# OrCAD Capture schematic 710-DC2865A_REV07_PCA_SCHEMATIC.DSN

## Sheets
1 PAGE2-HARDWARE
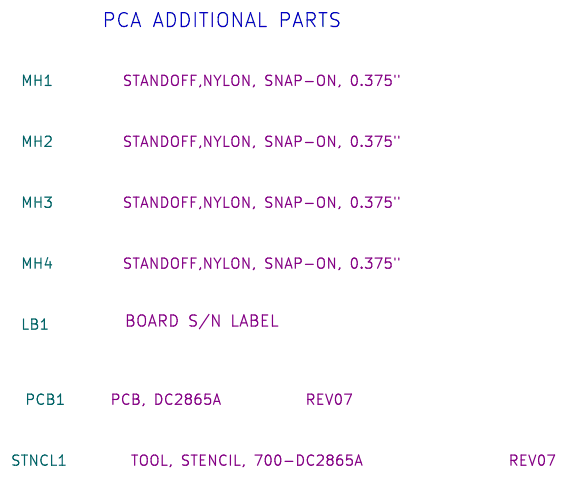
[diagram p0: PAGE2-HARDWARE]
2 PAGE1-LT8393JFE: size Custom; note: LED CONTROLLER
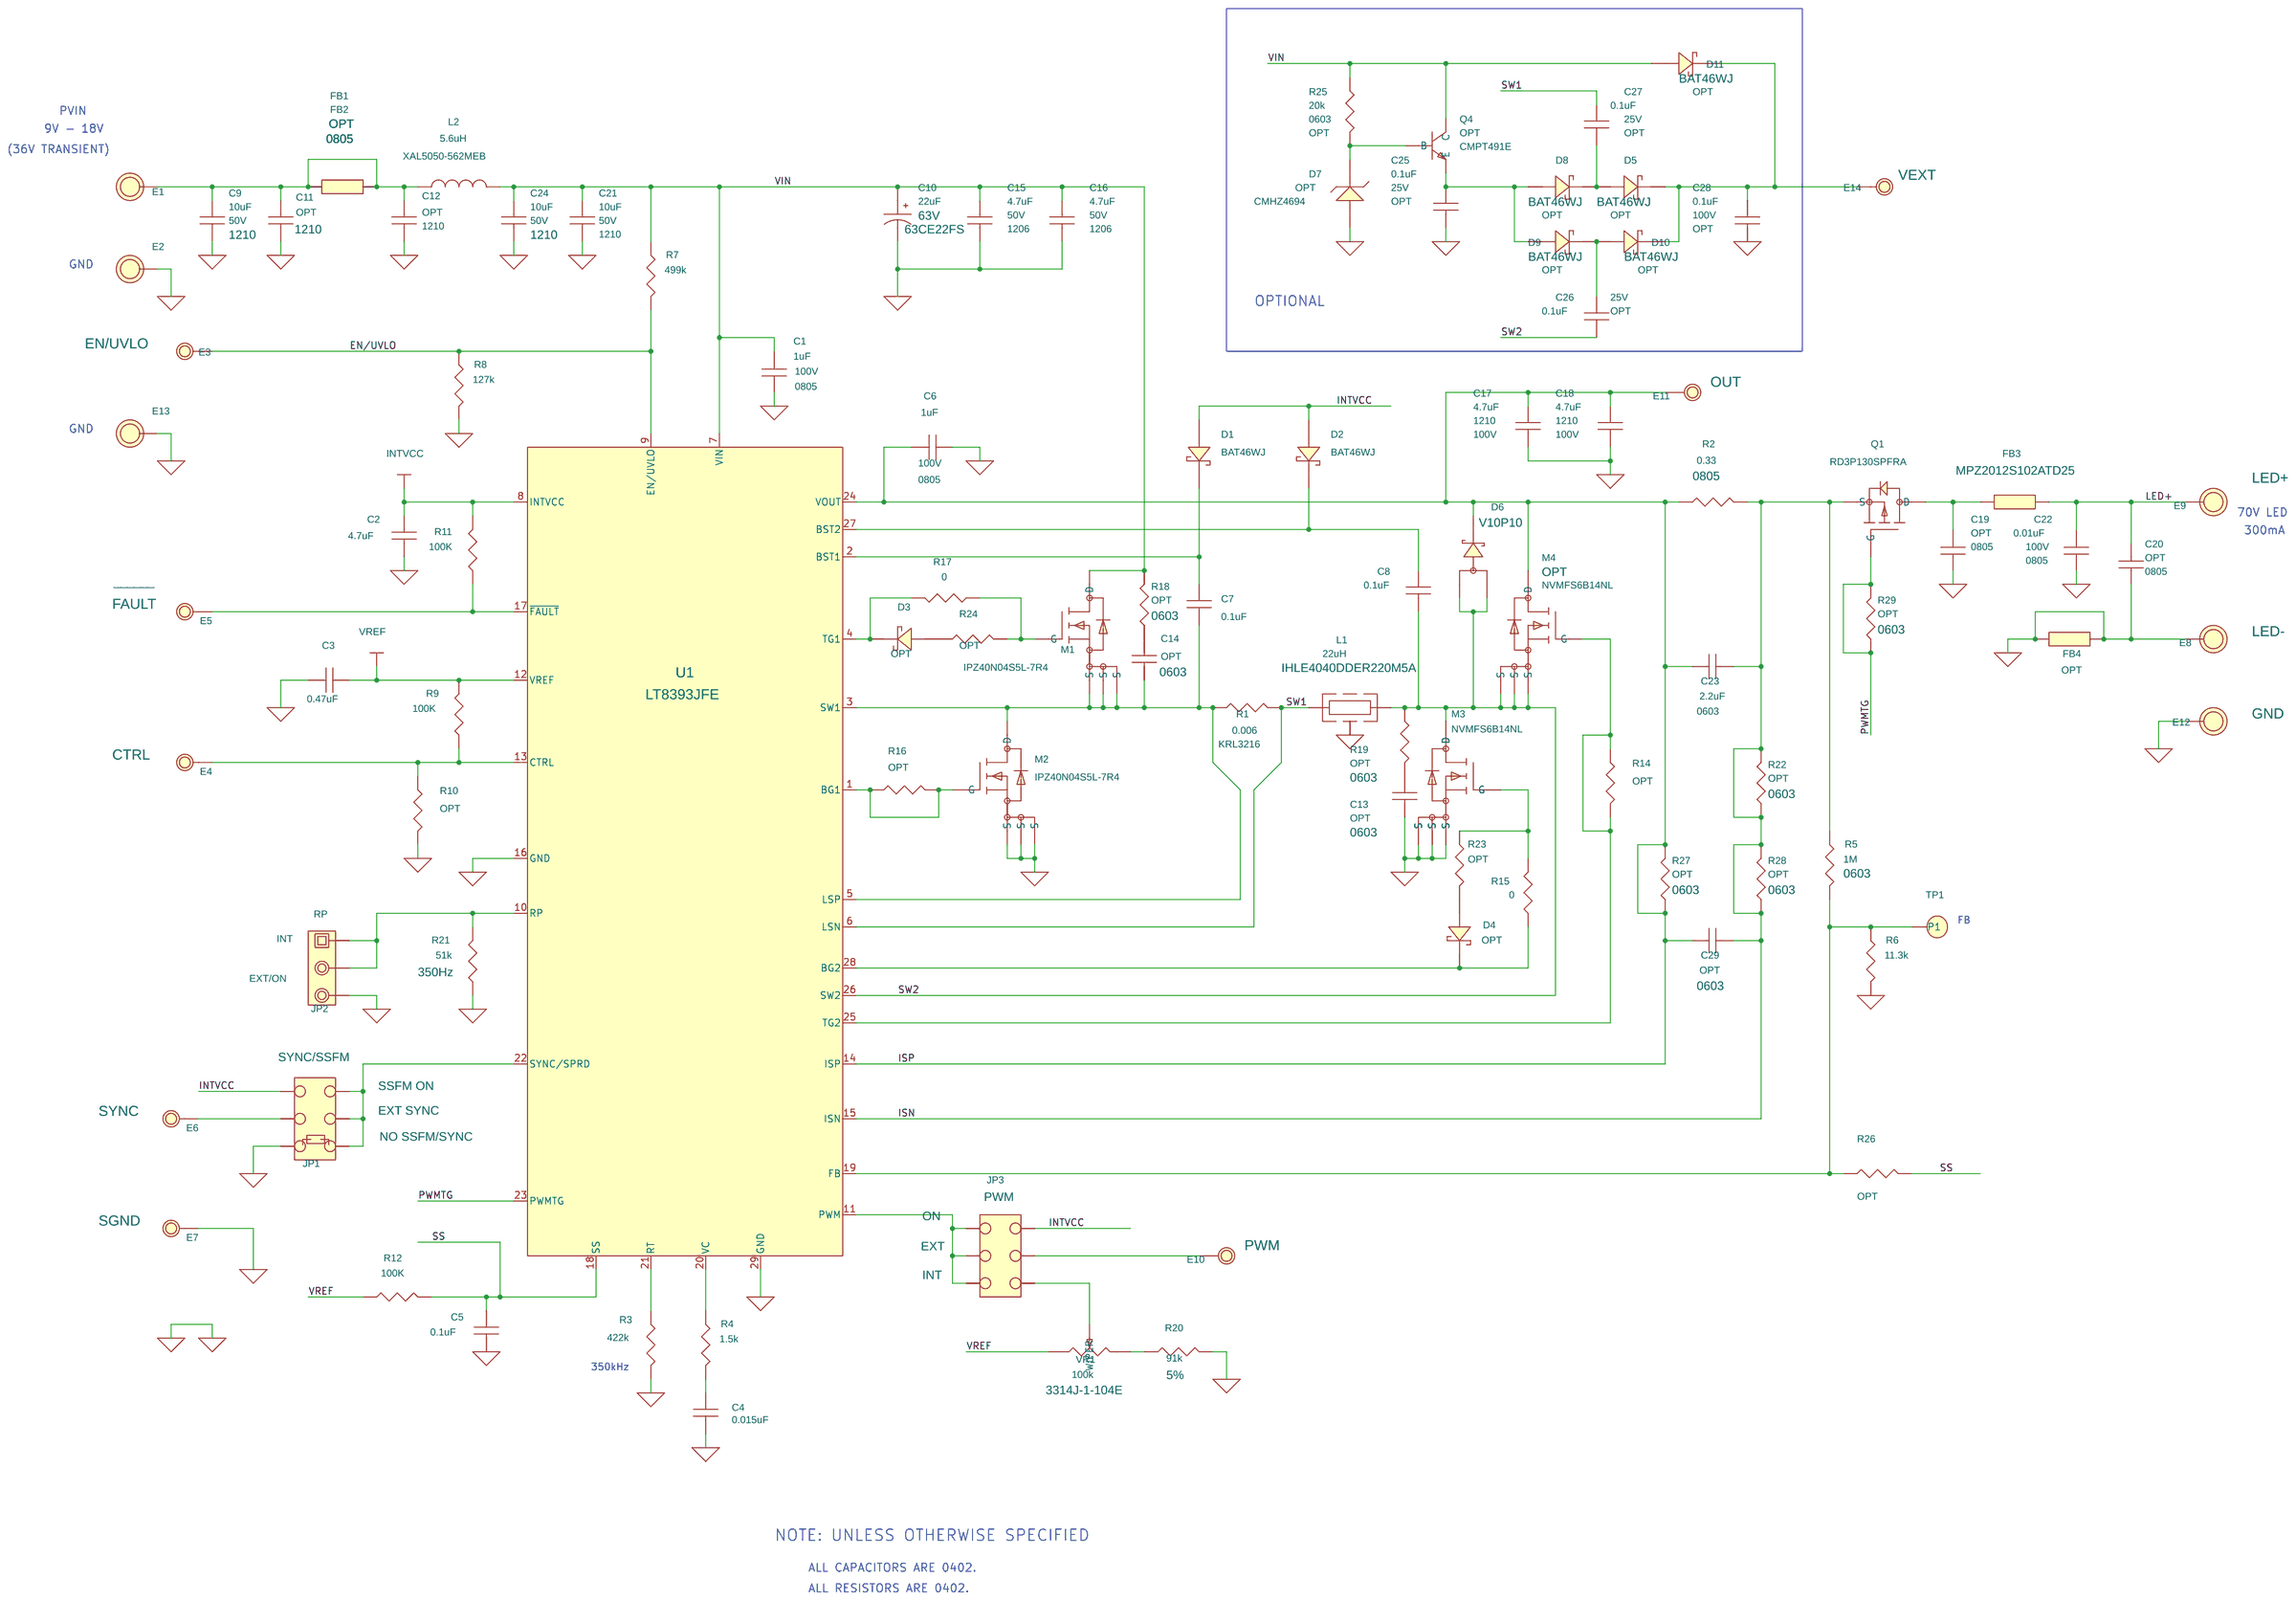
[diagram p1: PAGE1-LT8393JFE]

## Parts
sheet PAGE1-LT8393JFE
C1  1uF  [CC0805N]
C2  4.7uF  [CC0402N]
C3  0.47uF  [CC0402N]
C4  0.015uF  [CC0402N]
C5  0.1uF  [CC0402N]
C6  1uF  [CC0805N]
C7  0.1uF  [CC0402N]
C8  0.1uF  [CC0402N]
C9  10uF  [CC1210N]
C10  22uF  [SUNCON_CE-FS_6.3X7.7]
C11  OPT  [CC1210N]
C12  OPT  [CC1210N]
C13  OPT  [CC0603N]
C14  OPT  [CC0603N]
C15  4.7uF  [CC1206N]
C16  4.7uF  [CC1206N]
C17  4.7uF  [CC1210N]
C18  4.7uF  [CC1210N]
C19  OPT  [CC0805N]
C20  OPT  [CC0805N]
C21  10uF  [CC1210N]
C22  0.01uF  [CC0805N]
C23  2.2uF  [CC0603N]
C24  10uF  [CC1210N]
C25  0.1uF  [CC0402N]
C26  0.1uF  [CC0402N]
C27  0.1uF  [CC0402N]
C28  0.1uF  [CC0402N]
C29  OPT  [CC0603N]
D1  BAT46WJ  [SOD-323F-N]
D2  BAT46WJ  [SOD-323F-N]
D3  OPT  [SOD-523N]
D4  OPT  [SOD-523N]
D5  BAT46WJ  [SOD-323F-N]
D6  V10P10  [VISHAY-TO-277A_SMPC]
D7  OPT  [SOD-123N]
D8  BAT46WJ  [SOD-323F-N]
D9  BAT46WJ  [SOD-323F-N]
D10  BAT46WJ  [SOD-323F-N]
D11  BAT46WJ  [SOD-323F-N]
E1  TEST POINT  [MILLMAX2501]
E2  TEST POINT  [MILLMAX2501]
E3  TEST POINT  [MILLMAX2308]
E4  TEST POINT  [MILLMAX2308]
E5  TEST POINT  [MILLMAX2308]
E6  TEST POINT  [MILLMAX2308]
E7  TEST POINT  [MILLMAX2308]
E8  TEST POINT  [MILLMAX2501]
E9  TEST POINT  [MILLMAX2501]
E10  TEST POINT  [MILLMAX2308]
E11  TEST POINT  [MILLMAX2308]
E12  TEST POINT  [MILLMAX2501]
E13  TEST POINT  [MILLMAX2501]
E14  TEST POINT  [MILLMAX2308]
FB1  OPT  [IND0805N]
FB2  OPT  [IND0805N]
FB3  1k OHM@100MHz  [IND0805N]
FB4  1k OHM@100MHz  [IND0805N]
JP1  HDR  [HD2X3-079]
JP2  HDR  [HD1X3-079]
JP3  HDR  [HD2X3-079]
L1  22uH  [VISHAY-IHLE-4040DD-5A]
L2  5.6uH  [COILCRAFT-XAL50]
M1  IPZ40N04S5L-7R4  [INFINEON-PG-TSDSON-8-32]
M2  IPZ40N04S5L-7R4  [INFINEON-PG-TSDSON-8-32]
M3  NVMFS6B14NL  [ONSEMI-DFN5-SO-8FL]
M4  NVMFS6B14NL  [ONSEMI-DFN5-SO-8FL]
Q1  RD3P130SPFRA  [TO-252-3N]
Q4  OPT  [SOT23-3N]
R1  0.006  [SUSUMU-KRL3216]
R2  0.33  [CR0805N]
R3  422k  [CR0402N]
R4  1.5k  [CR0402N]
R5  1M  [CR0603N]
R6  11.3k  [CR0402N]
R7  499k  [CR0402N]
R8  127k  [CR0402N]
R9  100K  [CR0402N]
R10  OPT  [CR0402N]
R11  100K  [CR0402N]
R12  100K  [CR0402N]
R14  OPT  [CR0402N]
R15  0  [CR0402N]
R16  OPT  [CR0402N]
R17  0  [CR0402N]
R18  OPT  [CR0603N]
R19  OPT  [CR0603N]
R20  91k  [CR0402N]
R21  51k  [CR0402N]
R22  OPT  [CR0603N]
R23  OPT  [CR0402N]
R24  OPT  [CR0402N]
R25  20k  [CR0603N]
R26  OPT  [CR0402N]
R27  OPT  [CR0603N]
R28  OPT  [CR0603N]
R29  OPT  [CR0603N]
TP1  TEST PAD  [TEST-PIN]
U1  LT8393JFE  [LTC-FE-28-1663]
VR1  100k  [BOURNES-3314J]
XJP1  SHUNT
XJP2  SHUNT
XJP3  SHUNT
sheet PAGE2-HARDWARE
LB1  LABEL  [895-0154_REV01]
MH1  STANDOFF  [WURTH-7029]
MH2  STANDOFF  [WURTH-7029]
MH3  STANDOFF  [WURTH-7029]
MH4  STANDOFF  [WURTH-7029]
PCB1  PCB, DC2865A  [MECHANICAL_PART]
STNCL1  TOOL, STENCIL, 700-DC2865A

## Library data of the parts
C1 C6 = CAP: CAP.,1uF,X7S,100V,10%,0805,AEC-Q200,NO SUBS. ALLOWED; CLASS: DISCRETE; Dielectric Type: X7S; FPLIST: CC0805N,CC0805L,CC0805M; Inventory Qty: 11870; Manufacturer: MURATA; Manufacturer PN: GCM21BC72A105KE36L; PART_NUMBER: 150-1770; Package Size: 0805; Rated Voltage: 100V; Temperature Coefficient: X7S; Tolerance: 10%
C2 = CAP: CAP.,4.7uF,X5R,10V,10%,0402; CLASS: DISCRETE; Dielectric Type: X5R; FPLIST: CC0402N,CC0402L,CC0402M; Inventory Qty: 30305; Manufacturer: TDK; Manufacturer PN: C1005X5R1A475K050BC; PART_NUMBER: 150-2275; Package Size: 0402; Rated Voltage: 10V; Tolerance: 10%
C3 = CAP: CAP.,0.47uF,X5R,16V,10%,0402; CLASS: DISCRETE; Dielectric Type: X5R; Inventory Qty: 1178; Manufacturer: AVX; Manufacturer PN: 0402YD474KAT2A; PART_NUMBER: 150-3431; Package Size: 0402; Rated Voltage: 16V; Tolerance: 10%
C4 = CAP: CAP.,0.015uF,X7R,16V,10%,0402; CLASS: DISCRETE; Dielectric Type: X7R; Inventory Qty: 30000; Manufacturer: AVX; Manufacturer PN: 0402YC153KAT2A; PART_NUMBER: 150-2639; Package Size: 0402; Package Type: SMD; Rated Voltage: 16V; Tolerance: 10%
C5 C7 C8 = CAP: CAP.,0.1uF,X7R,25V,10%,0402; CLASS: DISCRETE; Dielectric Type: X7R; FPLIST: CC0402N,CC0402L,CC0402M; Inventory Qty: 44848; Manufacturer: AVX; Manufacturer PN: 04023C104KAT2A; PART_NUMBER: 150-2276; Package Size: 0402; Rated Voltage: 25V; Tolerance: 10%
C9 C24 = CAP: CAP.,10uF,X7S,50V,10%,1210,AEC-Q200; CLASS: DISCRETE; Dielectric Type: X7S; FPLIST: CC1210N,CC1210L,CC1210M; Inventory Qty: 0; Manufacturer: MURATA; Manufacturer PN: GCM32EC71H106KA03L; PART_NUMBER: 150-2617; Package Size: 1210; Rated Voltage: 50V; Tolerance: 10%
C10 = CAP_P_ALT: CAP.,22uF,ALUM,63V,20%,SMD 6.3x7.7mm; CLASS: DISCRETE; Dielectric Type: ALUM; Inventory Qty: 8770; Manufacturer: SUN ELECTRONIC INDUSTRIES CORP; Manufacturer PN: 63CE22FS; PART_NUMBER: 150-2277; Package Size: SMD 6.3x7.7mm; Rated Voltage: 63V; Tolerance: 20%
C11 C12 = CAP: CAP., OPTION, 1210; CLASS: DISCRETE; FPLIST: CC1210N,CC1210L,CC1210M; PART_NUMBER: 150-3035; Package Size: 1210; Package Type: SMD
C13 C14 C29 = CAP: CAP., OPTION, 0603; CLASS: DISCRETE; FPLIST: CC0603N,CC0603L,CC0603M; PART_NUMBER: 150-3038; Package Size: 0603; Package Type: SMD
C15 C16 = CAP: CAP.,4.7uF,X7S,50V,10%,1206,AEC-Q200; CLASS: DISCRETE; Dielectric Type: X7S; FPLIST: CC1206N,CC1206L,CC1206M; Inventory Qty: 7000; Manufacturer: MURATA; Manufacturer PN: GCM31CC71H475KA03K; PART_NUMBER: 150-0838; Package Size: 1206; Rated Voltage: 50V; Temperature Coefficient: X7S; Tolerance: 10%
C17 C18 = CAP: CAP.,4.7uF,X7S,100V,10%,1210,AEC-Q200,NO SUBS. ALLOWED; CLASS: DISCRETE; Dielectric Type: X7S; FPLIST: CC1210N,CC1210L,CC1210M; Inventory Qty: 4838; Manufacturer: MURATA; Manufacturer PN: GCM32DC72A475KE02L; PART_NUMBER: 150-2390; Package Size: 1210; Package Type: Surface Mount, MLCC; Rated Voltage: 100V; Tolerance: 10%
C19 C20 = CAP: CAP., OPTION, 0805; CLASS: DISCRETE; FPLIST: CC0805N,CC0805L,CC0805M; PART_NUMBER: 150-3036; Package Size: 0805; Package Type: SMD
C21 = CAP: CAP.,10uF,X7S,50V,10%,1210,AEC-Q200, NO SUBS ALLOWED; CLASS: DISCRETE; Dielectric Type: X7S; FPLIST: CC1210N,CC1210L,CC1210M; Inventory Qty: 10520; Manufacturer: MURATA; Manufacturer PN: GCM32EC71H106KA03L; PART_NUMBER: 150-2354; Package Size: 1210; Rated Voltage: 50V; Tolerance: 10%
C22 = CAP: CAP.,0.01uF,X7R,100V,10%,0805,AEC-Q200; CLASS: DISCRETE; Dielectric Type: X7R; FPLIST: CC0805N,CC0805L,CC0805M; Inventory Qty: 16320; Manufacturer: AVX; Manufacturer PN: 08051C103K4Z4A; PART_NUMBER: 150-0512; Package Size: 0805; Rated Voltage: 100V; Tolerance: 10%
C23 = CAP: CAP.,2.2uF,X7S,10V,10%,0603,AEC-Q200; CLASS: DISCRETE; Dielectric Type: X7S; FPLIST: CC0603N,CC0603L,CC0603M; Inventory Qty: 3800; Manufacturer: TDK; Manufacturer PN: CGA3E3X7S1A225K080AB; PART_NUMBER: 150-1791; Package Size: 0603; Rated Voltage: 10V; Tolerance: 10%
C25-C27 = CAP: CAP.,0.1uF,X5R,25V,10%,0402; 9th Part Field: OPT; CLASS: DISCRETE; Dielectric Type: X5R; FPLIST: CC0402N,CC0402L,CC0402M; Inventory Qty: 88178; Manufacturer: AVX; Manufacturer PN: 04023D104KAT2A; PART_NUMBER: 150-0249; Package Size: 0402; Rated Voltage: 25V; Tolerance: 10%
C28 = CAP: CAP.,0.1uF,X5R,100V,10%,0402,NO SUBS. ALLOWED; 9th Part Field: OPT; CLASS: DISCRETE; Dielectric Type: X5R; FPLIST: CC0402N,CC0402L,CC0402M; Inventory Qty: 79412; Manufacturer: MURATA; Manufacturer PN: GRM155R62A104KE14D; PART_NUMBER: 150-2279; Package Size: 0402; Package Type: SMD; Rated Voltage: 100V; Tolerance: 10%
D1 D2 = DIODE_SCHOTTKY_A_ALT: DIODE,SCHOTTKY,100V,250mA,SOD-323F,AEC-Q101; CLASS: DISCRETE; Inventory Qty: 6794; Manufacturer: NEXPERIA; Manufacturer PN: BAT46WJ,115; Max Forward Current or Rated Power: 250mA; PART_NUMBER: 210-0235; Package Type: SOD-323F; Rated Voltage or Zener Voltage: 100V
D3 D4 = DIODE_SCHOTTKY_A_ALT: DIODE, OPTION, SOD-523; CLASS: DISCRETE; FPLIST: SOD-523N,SOD-523L,SOD-523M; PART_NUMBER: 210-0143; Package Type: SOD-523
D5 D8-D11 = DIODE_SCHOTTKY_A_ALT: DIODE,SCHOTTKY,100V,250mA,SOD-323F,AEC-Q101; CLASS: DISCRETE; FPLIST: SOD-323F-N,SOD-323F-L,SOD-323F-M; Inventory Qty: 6794; Manufacturer: NEXPERIA; Manufacturer PN: BAT46WJ,115; Max Forward Current or Rated Power: 250mA; PART_FIELD_1: OPT; PART_NUMBER: 210-0235; Package Type: SOD-323F; Rated Voltage or Zener Voltage: 100V
D6 = DIODE_SCHOTTKY_PACKAGE4: DIODE,SCHOTTKY,100V,10A,SMPC (TO-277A),AEC-Q101; CLASS: DISCRETE; Inventory Qty: 1500; Manufacturer: VISHAY; Manufacturer PN: V10P10HM3_A/H; PART_NUMBER: 210-0542; Package Size: TO-277, 3-PowerDFN; Package Type: SMPC (TO-277A); Rated Voltage or Zener Voltage: 100V
D7 = ZENER_ALT: DIODE, OPTION, SOD-123; 9th Part Field: CMHZ4694; CLASS: DISCRETE; FPLIST: SOD-123N,SOD-123L,SOD-123M; PART_NUMBER: 210-0115; Package Type: SOD-123
E1 = TURRET_A: TEST POINT,TURRET,0.094" MTG. HOLE,PCB 0.062" THK; 9th Part Field: PVIN; CLASS: IO; Inventory Qty: 823526; Manufacturer: MILL-MAX; Manufacturer PN: 2501-2-00-80-00-00-07-0; PART_NUMBER: 260-0003
E2 E12 E13 = TURRET_A: TEST POINT,TURRET,0.094" MTG. HOLE,PCB 0.062" THK; 9th Part Field: GND; CLASS: IO; Inventory Qty: 823526; Manufacturer: MILL-MAX; Manufacturer PN: 2501-2-00-80-00-00-07-0; PART_NUMBER: 260-0003
E3 = TEST_POINT_.156_MILL-MAX_2308_A: TEST POINT,TURRET,0.064" MTG. HOLE,PCB 0.062" THK; 10th Part Field: 5.8V - 40V; 1st Part Field: EN/UVLO; CLASS: IO; Inventory Qty: 1142083; Manufacturer: MILL-MAX; Manufacturer PN: 2308-2-00-80-00-00-07-0; PART_NUMBER: 260-0004
E4 = TEST_POINT_.156_MILL-MAX_2308_A: TEST POINT,TURRET,0.064" MTG. HOLE,PCB 0.062" THK; 10th Part Field: ______; 1st Part Field: CTRL; CLASS: IO; Inventory Qty: 1142083; Manufacturer: MILL-MAX; Manufacturer PN: 2308-2-00-80-00-00-07-0; PART_NUMBER: 260-0004
E5 = TEST_POINT_.156_MILL-MAX_2308_A: TEST POINT,TURRET,0.064" MTG. HOLE,PCB 0.062" THK; 10th Part Field: ______; 1st Part Field: FAULT; CLASS: IO; Inventory Qty: 1142083; Manufacturer: MILL-MAX; Manufacturer PN: 2308-2-00-80-00-00-07-0; PART_NUMBER: 260-0004
E6 = TEST_POINT_.156_MILL-MAX_2308_A: TEST POINT,TURRET,0.064" MTG. HOLE,PCB 0.062" THK; 10th Part Field: ______; 1st Part Field: SYNC; CLASS: IO; Inventory Qty: 1142083; Manufacturer: MILL-MAX; Manufacturer PN: 2308-2-00-80-00-00-07-0; PART_NUMBER: 260-0004
E7 = TEST_POINT_.156_MILL-MAX_2308_A: TEST POINT,TURRET,0.064" MTG. HOLE,PCB 0.062" THK; 10th Part Field: ______; 1st Part Field: SGND; CLASS: IO; Inventory Qty: 1142083; Manufacturer: MILL-MAX; Manufacturer PN: 2308-2-00-80-00-00-07-0; PART_NUMBER: 260-0004
E8 = TURRET_A: TEST POINT,TURRET,0.094" MTG. HOLE,PCB 0.062" THK; 9th Part Field: LED-; CLASS: IO; Inventory Qty: 823526; Manufacturer: MILL-MAX; Manufacturer PN: 2501-2-00-80-00-00-07-0; PART_NUMBER: 260-0003
E9 = TURRET_A: TEST POINT,TURRET,0.094" MTG. HOLE,PCB 0.062" THK; 9th Part Field: LED+; CLASS: IO; Inventory Qty: 823526; Manufacturer: MILL-MAX; Manufacturer PN: 2501-2-00-80-00-00-07-0; PART_NUMBER: 260-0003
E10 = TEST_POINT_.156_MILL-MAX_2308_A: TEST POINT,TURRET,0.064" MTG. HOLE,PCB 0.062" THK; 10th Part Field: ______; 1st Part Field: PWM; CLASS: IO; Inventory Qty: 1142083; Manufacturer: MILL-MAX; Manufacturer PN: 2308-2-00-80-00-00-07-0; PART_NUMBER: 260-0004
E11 = TEST_POINT_.156_MILL-MAX_2308_A: TEST POINT,TURRET,0.064" MTG. HOLE,PCB 0.062" THK; 10th Part Field: ______; 1st Part Field: OUT; CLASS: IO; Inventory Qty: 1142083; Manufacturer: MILL-MAX; Manufacturer PN: 2308-2-00-80-00-00-07-0; PART_NUMBER: 260-0004
E14 = TEST_POINT_.156_MILL-MAX_2308_A: TEST POINT,TURRET,0.064" MTG. HOLE,PCB 0.062" THK; 10th Part Field: ______; 1st Part Field: VEXT; CLASS: IO; Inventory Qty: 1142083; Manufacturer: MILL-MAX; Manufacturer PN: 2308-2-00-80-00-00-07-0; PART_NUMBER: 260-0004
FB1 FB2 = FERRITEBEAD_ALT1: IND.,FERRITE BEAD,OPT,0805; CLASS: DISCRETE; FPLIST: IND0805N,IND0805L,IND0805M; PART_NUMBER: 200-0529; Package Size: 0805
FB3 = FERRITEBEAD_ALT1: IND.,1k OHM@100MHz,FERRITE BEAD,25%,1.5A,150mOHMS,0805,AEC-Q200; CLASS: DISCRETE; Inventory Qty: 23804; Manufacturer: TDK; Manufacturer PN: MPZ2012S102ATD25; PART_NUMBER: 200-0508; Package Size: 0805; Tolerance: 25%
FB4 = FERRITEBEAD_ALT1: IND.,1k OHM@100MHz,FERRITE BEAD,25%,1.5A,150mOHMS,0805,AEC-Q200; 9th Part Field: OPT; CLASS: DISCRETE; Inventory Qty: 23804; Manufacturer: TDK; Manufacturer PN: MPZ2012S102ATD25; PART_NUMBER: 200-0508; Package Size: 0805; Tolerance: 25%
JP1 = HEADER_2X3_.079: CONN.,HDR,MALE,2x3,2mm,VERT,ST,THT; 10th Part Field: EXT SYNC; 11th Part Field: NO SSFM/SYNC; 13tht Part Field: SYNC/SSFM; 9th Part Field: SSFM ON; CLASS: IO; FPLIST: HD2X3-079,WURTH-62000621121; Inventory Qty: 17651; Manufacturer: WURTH ELEKTRONIK; Manufacturer PN: 62000621121; PART_NUMBER: 250-0483
JP2 = 1X3_A: CONN.,HDR,MALE,1x3,2mm,VERT,ST,THT,NO SUBS. ALLOWED; 10th Part Field: EXT/ON; 12th Part Field: RP; 9th Part Field: INT; CLASS: IO; Inventory Qty: 28997; Manufacturer: Wurth Elektronik; Manufacturer PN: 62000311121; PART_NUMBER: 250-0639
JP3 = HEADER_2X3_.079: CONN.,HDR,MALE,2x3,2mm,VERT,ST,THT; 10th Part Field: EXT; 11th Part Field: INT; 12th Part Field: 12th???; 13tht Part Field: PWM; 9th Part Field: ON; CLASS: IO; FPLIST: HD2X3-079,WURTH-62000621121; Inventory Qty: 17651; Manufacturer: WURTH ELEKTRONIK; Manufacturer PN: 62000621121; PART_NUMBER: 250-0483
L1 = IND_4-PIN_SHIELDED: IND.,22uH,PWR,SHIELDED,20%,4.1A,75.44mOHMS,4040DD,IHLE-5A Series,AEC-Q200; CLASS: DISCRETE; Inventory Qty: 0; Manufacturer: VISHAY; Manufacturer PN: IHLE4040DDER220M5A; PART_NUMBER: 200-0829; Package Size: 4040DD; Tolerance: 20%
L2 = IND_ALT: IND.,5.6uH,PWR,SHIELDED,20%,7.2A,25.80mOHMS,5.28x5.48mm,AEC-Q200; CLASS: DISCRETE; Inventory Qty: 0; Manufacturer: COILCRAFT; Manufacturer PN: XAL5050-562MEB; PART_NUMBER: 200-0528; Package Size: 5.28x5.48mm; Tolerance: 20%
M1 M2 = 5P_N-CH_TYPE1C: XSTR.,MOSFET,N-CH,40V,40A,PG-TSDSON-8-32,AEC-Q101; CLASS: DISCRETE; Inventory Qty: 4360; Manufacturer: INFINEON; PART_NUMBER: 240-0288; Package Size: 8-PowerTDFN; Package Type: PG-TSDSON-8-32; Rated Voltage: 40V
M3 = 5P_N-CH_TYPE1C: XSTR.,MOSFET,N-CH,100V,11A,DFN5 (SO-8FL),AEC-Q101; CLASS: DISCRETE; Inventory Qty: 0; Manufacturer: ON Semiconductor; Manufacturer PN: NVMFS6B14NLT1G; PART_NUMBER: 240-0372; Package Size: 8-PowerTDFN; Package Type: DFN5 (SO-8FL); Polarity: N-Channel; Rated Voltage: 100V
M4 = 5P_N-CH_TYPE1C: XSTR.,MOSFET,N-CH,100V,11A,DFN5 (SO-8FL),AEC-Q101; 9th Part Field: OPT; CLASS: DISCRETE; Inventory Qty: 0; Manufacturer: ON Semiconductor; Manufacturer PN: NVMFS6B14NLT1G; PART_NUMBER: 240-0372; Package Size: 8-PowerTDFN; Package Type: DFN5 (SO-8FL); Polarity: N-Channel; Rated Voltage: 100V
Q1 = 3P_P-CH_TYPE2A: XSTR.,MOSFET,P-CH,100V,13A,DPAK (TO-252),AEC-Q101; CLASS: DISCRETE; Inventory Qty: 2500; Manufacturer: ROHM; Manufacturer PN: RD3P130SPFRATL; PART_NUMBER: 240-0468; Package Size: TO-252; Package Type: DPAK (TO-252); Rated Power: 20W (Tc); Rated Voltage: 100V
Q4 = 3P_NPN_TYPE1A: XSTR., OPTION, NPN, SOT-23; 9th Part Field: CMPT491E; CLASS: DISCRETE; FPLIST: SOT23-3N,SOT23-3L,SOT23-3M; PART_NUMBER: 240-0169; Package Type: SOT-23
R1 = RES: RES.,0.006 OHM,1%,1.5W,1206, LONG-SIDE TERM.,HIGH TEMP., SENSE, AEC-Q200; 3rd Part Field: KRL3216; CLASS: DISCRETE; Inventory Qty: 3332; Manufacturer: SUSUMU; Manufacturer PN: KRL3216E-C-R006-F-T1; PART_NUMBER: 100-0513; Package Size: 1206, LONG-SIDE TERM.; Rated Power: 1.5W; Temperature Coefficient: 50ppm; Tolerance: 1%
R2 = RES: RES.,0.33 OHM,1%,1/3W,0805,SHORT-SIDE TERM.,SENSE; 9th Part Field: 0805; CLASS: DISCRETE; Inventory Qty: 0; Manufacturer: Susumu; Manufacturer PN: RL1220S-R33-F; PART_NUMBER: 100-1180; Package Size: 0805,SHORT-SIDE TERM.; Rated Power: 1/3W; Temperature Coefficient: 0~ +200ppm; Tolerance: 1%
R3 = RES: RES.,422k OHMS,1%,1/16W,0402,AEC-Q200; CLASS: DISCRETE; FPLIST: CR0402N,CR0402L,CR0402M; Inventory Qty: 21118; Manufacturer: NIC; Manufacturer PN: NRC04F4223TRF; PART_NUMBER: 100-0397; Package Size: 0402; Rated Power: 1/16W; Temperature Coefficient: 100ppm; Tolerance: 1%
R4 = RES: RES.,1.5k OHMS,1%,1/16W,0402,AEC-Q200; CLASS: DISCRETE; FPLIST: CR0402N,CR0402L,CR0402M; Inventory Qty: 60252; Manufacturer: NIC; Manufacturer PN: NRC04F1501TRF; PART_NUMBER: 100-2689; Package Size: 0402; Rated Power: 1/16W; Temperature Coefficient: 100ppm; Tolerance: 1%
R5 = RES: RES.,1M OHM,1%,1/10W,0603,AEC-Q200; CLASS: DISCRETE; FPLIST: CR0603N,CR0603L,CR0603M; Inventory Qty: 165718; Manufacturer: VISHAY; Manufacturer PN: CRCW06031M00FKEA; PART_NUMBER: 100-0335; Package Size: 0603; Rated Power: 1/10W; Temperature Coefficient: 100ppm; Tolerance: 1%
R6 = RES: RES.,11.3k OHMS,1%,1/16W,0402,AEC-Q200; CLASS: DISCRETE; FPLIST: CR0402N,CR0402L,CR0402M; Inventory Qty: 33516; Manufacturer: NIC; Manufacturer PN: NRC04F1132TRF; PART_NUMBER: 100-2989; Package Size: 0402; Rated Power: 1/16W; Temperature Coefficient: +/-100; Tolerance: 1%
R7 = RES: RES.,499k OHMS,1%,1/16W,0402,AEC-Q200; CLASS: DISCRETE; Inventory Qty: 39488; Manufacturer: NIC; Manufacturer PN: NRC04F4993TRF; PART_NUMBER: 100-2665; Package Size: 0402; Rated Power: 1/16W; Temperature Coefficient: 100ppm; Tolerance: 1%
R8 = RES: RES.,127k OHMS,1%,1/16W,0402; CLASS: DISCRETE; FPLIST: CR0402N,CR0402L,CR0402M; Inventory Qty: 0; Manufacturer: VISHAY; Manufacturer PN: CRCW0402127KFKED; PART_NUMBER: 100-2516; Package Size: 0402; Rated Power: 1/16W; Temperature Coefficient: 100ppm/C; Tolerance: 1%
R9 R11 R12 = RES: RES.,100k OHMS,1%,1/16W,0402,AEC-Q200; CLASS: DISCRETE; FPLIST: CR0402N,CR0402L,CR0402M; Inventory Qty: 92256; Manufacturer: NIC; Manufacturer PN: NRC04F1003TRF; PART_NUMBER: 100-0601; Package Size: 0402; Rated Power: 1/16W; Temperature Coefficient: 100PPM; Tolerance: 1%
R10 R14 R16 R23 R24 R26 = RES: RES., OPTION, 0402; CLASS: DISCRETE; FPLIST: CR0402N,CR0402L,CR0402M; PART_NUMBER: 100-0357; Package Size: 0402
R15 R17 = RES: RES.,0 OHM,1/16W,0402; CLASS: DISCRETE; Inventory Qty: 264417; Manufacturer: ROHM; Manufacturer PN: MCR01MZPJ000; PART_NUMBER: 100-0215; Package Size: 0402; Rated Power: 1/16W
R18 R19 R22 R27-R29 = RES: RES., OPTION, 0603; CLASS: DISCRETE; FPLIST: CR0603N,CR0603L,CR0603M; PART_NUMBER: 100-2374; Package Size: 0603
R20 = RES: RES.,91k OHMS,5%,1/16W,0402,AEC-Q200; CLASS: DISCRETE; FPLIST: CR0402N,CR0402L,CR0402M; Inventory Qty: 59752; Manufacturer: NIC; Manufacturer PN: NRC04J913TRF; PART_NUMBER: 100-0520; Package Size: 0402; Rated Power: 1/16W; Temperature Coefficient: 200ppm; Tolerance: 5%
R21 = RES: RES.,51k OHMS,1%,1/16W,0402,AEC-Q200; 3rd Part Field: 350Hz; CLASS: DISCRETE; FPLIST: CR0402N,CR0402L,CR0402M; Inventory Qty: 70000; Manufacturer: NIC; Manufacturer PN: NRC04F5102TRF; PART_NUMBER: 100-2085; Package Size: 0402; Rated Power: 1/16W; Temperature Coefficient: +/-100PPM; Tolerance: 1%
R25 = RES: RES.,20k OHMS,1%,1/10W,0603; 9th Part Field: OPT; CLASS: DISCRETE; FPLIST: CR0603N,CR0603L,CR0603M; Inventory Qty: 145296; Manufacturer: NIC; Manufacturer PN: NRC06F2002TRF; PART_NUMBER: 100-2117; Package Size: 0603; Rated Power: 1/10W; Temperature Coefficient: +/-100PPM; Tolerance: 1%
TP1 = PCB_TP_COPPER_FEATURE: PCB PAD COPPER FEATURE; CLASS: DISCRETE; Manufacturer: N/A; Manufacturer PN: N/A
U1 = LT8393-FE: IC,LED DRIVER CTRLR,TSSOP-28; CLASS: IC; Inventory Qty: 0; Manufacturer: ANALOG DEVICES; Manufacturer PN: LT8393JFE#WPBF; PART_NUMBER: LT8393JFE#WPBF; Package Size: 28-TSSOP (0.173", 4.40mm Width) Exposed Pad; Package Type: TSSOP-28
VR1 = TRIMPOT: RES.,100k OHMS,20%,1/4W,SMD 4mm SQ,1-TURN,TOP ADJ.,TRIMPOT; CLASS: DISCRETE; Inventory Qty: 12783; Manufacturer: BOURNS; Manufacturer PN: 3314J-1-104E; PART_NUMBER: 103-0025; Package Size: SMD 4mm SQ; Rated Power: 1/4W; Temperature Coefficient: 100ppm; Tolerance: 20%
XJP1-XJP3 = SHUNT_2MM_C: CONN.,SHUNT,FEMALE,2 POS,2mm; CLASS: IO; Inventory Qty: 64675; Manufacturer: Wurth Elektronik; Manufacturer PN: 60800213421; PART_NUMBER: 250-0485
LB1 = BLANK_LABEL: LABEL SPEC, DEMO BOARD SERIAL NUMBER; Inventory Qty: 0; Manufacturer: BRADY; Manufacturer PN: THT-96-717-10; PART_FIELD_01: BOARD S/N LABEL; PART_NUMBER: 895-0154
MH1-MH4 = BLANK_PINLESS_MECHANICAL_PART: STANDOFF,NYLON, SNAP-ON, 0.375"; CLASS: DISCRETE; Inventory Qty: 3800; Manufacturer: WURTH ELEKTRONIK; Manufacturer PN: 702933000; PART_NUMBER: 763-0021
PCB1 = BLANK_PCB_PART: BOM Notes: REV07; CLASS: DISCRETE; Inventory Qty: 0; Manufacturer: ADI APPROVED SUPPLIER; Manufacturer PN: 600-DC2865A; PART_NUMBER: 600-DC2865A
STNCL1 = BLANK_STENCIL_PART: BOM Notes: REV07; CLASS: DISCRETE; Inventory Qty: 0; Manufacturer: ADI APPROVED SUPPLIER; Manufacturer PN: 830-DC2865A; PART_NUMBER: 830-DC2865A

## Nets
GND: C1.1 C2.2 C3.2 C4.2 C5.2 C6.1 C9.2 C10.2 C11.2 C12.2 C13.2 C15.2 C16.2 C17.2 C18.2 C19.1 C20.1 C21.2 C22.1 C24.2 C25.2 C28.2 D7.2(A) E2.1 E7.1 E8.1 E12.1 E13.1 FB4.1 FB4.2 JP1.5 JP2.3 L1.3 L1.4 M2.1(S) M2.2(S) M2.3(S) M3.1(S) M3.2(S) M3.3(S) R3.2 R6.2 R8.2 R10.2 R20.2 R21.2 U1.16(GND) U1.29(GND)
VIN: C1.2 C10.1 C15.1 C16.1 C21.1 C24.1 D11.2(A) L2.2 M1.5(D) Q4.3(C) R7.1 R18.1 R25.2 U1.7(VIN)
EN/UVLO: E3.1 R7.2 R8.1 U1.9(EN/UVLO)
INTVCC: C2.1 D1.2(A) D2.2(A) JP1.1 JP3.2 R11.1 U1.8(INTVCC)
ISN: C23.2 C29.2 Q1.3(S) R2.2 R5.1 R22.1 R22.2 R28.1 R28.2 U1.15(ISN)
ISP: C6.2 C17.1 C18.1 C23.1 C29.1 D6.3 E11.1 M4.5(D) R2.1 R27.1 R27.2 U1.14(ISP) U1.24(VOUT)
LED+: C20.2 C22.2 E9.1 FB3.2
PWMTG: Q1.1(G) R29.1 R29.2 U1.23(PWMTG)
SS: C5.1 R12.1 R26.2 U1.18(SS)
SW1: C27.1 L1.2 R1.2 U1.6(LSN)
SW2: C8.2 C26.2 D6.1 D6.2 L1.1 M3.5(D) M4.1(S) M4.2(S) M4.3(S) R19.1 U1.26(SW2)
VREF: C3.1 R9.1 R12.2 U1.12(VREF) VR1.1
N16994718: C7.1 D1.1(C) U1.2(BST1)
N17009346: C4.1 R4.2
N17454578: C7.2 C14.2 M1.1(S) M1.2(S) M1.3(S) M2.5(D) R1.1 U1.3(SW1) U1.5(LSP)
N17508110: M2.4(G) R16.1 R16.2 U1.1(BG1)
N17509789: D3.1(C) R17.1 U1.4(TG1)
N17718651: M4.4(G) R14.1 R14.2 U1.25(TG2)
N17732267: C8.1 D2.1(C) U1.27(BST2)
N17841959: E5.1 R11.2 U1.17(~{FAULT})
N17844661: JP1.2 JP1.4 JP1.6 U1.22(SYNC/SPRD)
N17844682: E6.1 JP1.3
N17868488: R4.1 U1.20(VC)
N17869628: R5.2 R6.1 R26.1 TP1.1(P1) U1.19(FB)
N17916920: C9.1 C11.1 C12.1 E1.1 FB1.1 FB1.2 FB2.1 FB2.2 L2.1
N17925589: E4.1 R9.2 R10.1 U1.13(CTRL)
N17936306: M3.4(G) R15.1 R23.1
N17994936: R3.1 U1.21(RT)
N17997565: JP2.1 JP2.2 R21.1 U1.10(RP)
N18001060: C19.2 FB3.1 Q1.2(D)
N18013170: M1.4(G) R17.2 R24.2
N18013671: D4.1(C) R15.2 U1.28(BG2)
N18105608: JP3.6 VR1.2(WIPER)
N18105666: R20.1 VR1.3
N18106245: JP3.1 JP3.3 JP3.5 U1.11(PWM)
N18148941: E10.1 JP3.4
N18352105: D7.1(C) Q4.1(B) R25.1
N18352109: C27.2 D5.2(A) D8.1(C)
N18352121: C25.1 D8.2(A) D9.2(A) Q4.2(E)
N18352154: C28.1 D5.1(C) D10.1(C) D11.1(C) E14.1
N18352217: C26.1 D9.1(C) D10.2(A)
N18369770: D3.2(A) R24.1
N18369771: D4.2(A) R23.2
N18369772: C13.1 R19.2
N18369773: C14.1 R18.2

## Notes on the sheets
sheet 1
- PCA ADDITIONAL PARTS
sheet 2
- PVIN
- 9V - 18V
- (36V TRANSIENT)
- GND
- OPTIONAL
- GND
- 70V LED
- 300mA
- FB
- 350kHz
- NOTE: UNLESS OTHERWISE SPECIFIED
- ALL CAPACITORS ARE 0402.
- ALL RESISTORS ARE 0402.
